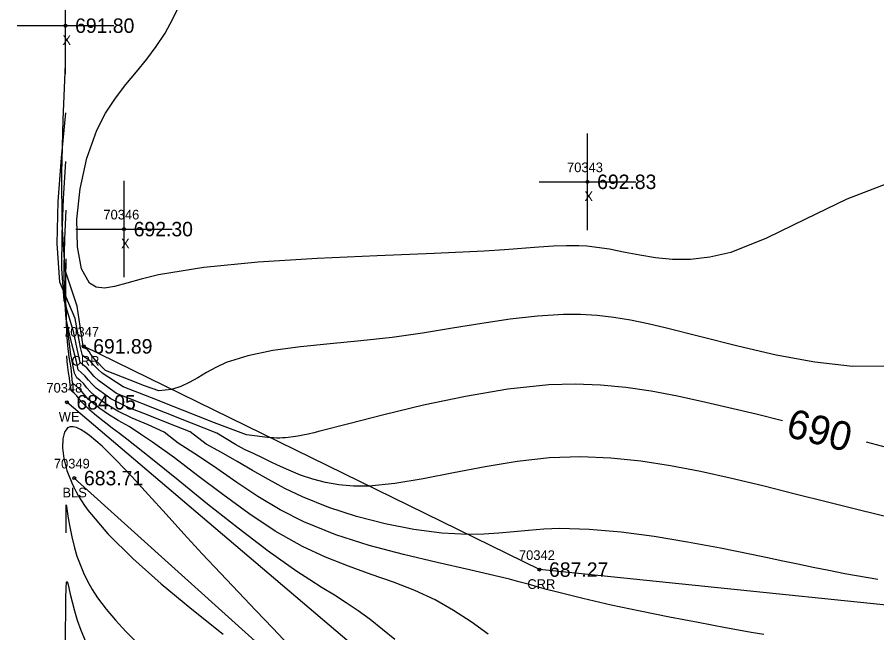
# Model space of a CAD drawing. Extents: x 1376587 to 1378239, y 1000335 to 1003031.
# Drawn here: x 1376921.1 to 1377010.1, y 1001560.2 to 1001624.1 of the extents above; entities that cross this region are included whole.
import ezdxf

# ---------------------------------------------------------------- set-up
doc = ezdxf.new("R2010")
doc.units = 0
for name, color, linetype in [('RD_DTM_BkLn1', 7, 'Continuous'), ('RD_DTM_BkLn_txCode', 7, 'Continuous'), ('RD_DTM_Major1', 7, 'Continuous'), ('RD_DTM_Major1_Lbl', 7, 'Continuous'), ('RD_DTM_Minor1', 7, 'Continuous'), ('RD_EX_H2O', 7, 'Continuous'), ('RD_EX_H2O_txCode', 7, 'Continuous'), ('RD_EX_Misc', 7, 'Continuous'), ('RD_EX_Misc_txCode', 7, 'Continuous'), ('RD_EX_TX_H2O_ELEV', 7, 'Continuous'), ('RD_EX_TX_Misc_ELEV', 7, 'Continuous'), ('RD_SMD_Locator', 7, 'Continuous')]:
    doc.layers.add(name, color=color, linetype=linetype)

msp = doc.modelspace()

# ---------------------------------------------------------------- linework, layer by layer
at = {"layer": 'RD_DTM_BkLn1'}
msp.add_lwpolyline([(1377322.969, 1001642.525), (1377293.605, 1001607.098), (1377249.432, 1001558.553), (1377170.427, 1001571.461), (1377111.377, 1001551.766), (1377054.733, 1001532.92), (1377033.73, 1001527.24), (1376971.435, 1001536.185), (1376926.988, 1001576.278)], dxfattribs=at)
at = {"layer": 'RD_DTM_Major1'}
for points in [[(1377000.334, 1001582.221), (1376997.598, 1001582.904), (1376992.398, 1001584.13), (1376989.479, 1001584.764), (1376986.737, 1001585.286), (1376984.1, 1001585.679), (1376981.502, 1001585.928), (1376978.871, 1001586.017), (1376976.139, 1001585.93), (1376971.904, 1001585.484), (1376967.51, 1001584.744), (1376963.162, 1001583.824), (1376959.062, 1001582.84), (1376955.414, 1001581.903), (1376952.422, 1001581.129), (1376951.799, 1001580.975), (1376951.22, 1001580.838), (1376950.674, 1001580.72), (1376950.152, 1001580.621), (1376949.642, 1001580.542), (1376949.135, 1001580.483), (1376948.85, 1001580.46), (1376948.56, 1001580.443), (1376948.261, 1001580.434), (1376947.952, 1001580.433), (1376947.629, 1001580.44), (1376947.29, 1001580.456), (1376944.84, 1001580.749), (1376941.5, 1001582.016), (1376938.18, 1001583.329), (1376934.972, 1001584.596), (1376932.063, 1001585.747), (1376929.864, 1001587.148), (1376929.433, 1001587.558), (1376929.027, 1001587.98), (1376928.645, 1001588.417), (1376928.153, 1001588.749), (1376927.824, 1001588.986), (1376927.641, 1001589.822), (1376927.095, 1001592.833), (1376925.495, 1001596.579), (1376925.218, 1001600.613), (1376925.31, 1001604.95), (1376925.647, 1001609.49), (1376926.106, 1001614.13)], [(1376960.172, 1001559.561), (1376957.617, 1001561.634), (1376956.382, 1001562.524), (1376955.155, 1001563.346), (1376953.923, 1001564.131), (1376952.67, 1001564.914), (1376951.381, 1001565.728), (1376950.043, 1001566.606), (1376947.072, 1001568.713), (1376943.947, 1001571.091), (1376940.794, 1001573.592), (1376937.742, 1001576.062), (1376934.917, 1001578.352), (1376932.446, 1001580.31), (1376931.653, 1001580.918), (1376930.923, 1001581.47), (1376930.254, 1001581.976), (1376929.646, 1001582.446), (1376929.095, 1001582.888), (1376928.602, 1001583.313), (1376928.203, 1001583.689), (1376927.848, 1001584.063), (1376927.536, 1001584.439), (1376927.264, 1001584.821), (1376926.978, 1001585.068), (1376926.681, 1001585.324), (1376926.563, 1001585.932), (1376926.506, 1001586.667), (1376926.399, 1001587.221), (1376926.318, 1001587.788), (1376926.254, 1001588.364), (1376926.199, 1001588.945)], [(1377014.23, 1001578.619), (1377009.053, 1001579.989)], [(1376926.158, 1001570.618), (1376926.138, 1001572.011), (1376926.133, 1001572.606), (1376926.133, 1001573.079), (1376926.141, 1001573.389), (1376926.158, 1001573.496), (1376926.196, 1001573.318), (1376926.261, 1001572.84), (1376926.363, 1001572.118), (1376926.514, 1001571.21), (1376926.723, 1001570.172), (1376927.001, 1001569.06), (1376927.265, 1001568.199), (1376927.579, 1001567.331), (1376927.946, 1001566.461), (1376928.37, 1001565.593), (1376928.854, 1001564.729), (1376929.403, 1001563.873), (1376930.278, 1001562.699), (1376931.262, 1001561.538), (1376932.335, 1001560.383), (1376933.473, 1001559.224)]]:
    msp.add_lwpolyline(points, dxfattribs=at)
at = {"layer": 'RD_DTM_Minor1'}
for points in [[(1377011.508, 1001606.935), (1377007.009, 1001605.182), (1377002.717, 1001603.12), (1376998.688, 1001601.152), (1376994.979, 1001599.681), (1376992.822, 1001599.164), (1376990.808, 1001598.941), (1376988.931, 1001598.947), (1376987.184, 1001599.116), (1376985.562, 1001599.382), (1376984.057, 1001599.681), (1376983.232, 1001599.845), (1376982.431, 1001599.993), (1376981.644, 1001600.122), (1376980.858, 1001600.227), (1376980.06, 1001600.305), (1376979.239, 1001600.351), (1376977.976, 1001600.358), (1376976.607, 1001600.305), (1376975.099, 1001600.208), (1376971.548, 1001599.94), (1376969.443, 1001599.802), (1376964.274, 1001599.554), (1376958.375, 1001599.322), (1376952.157, 1001599.045), (1376946.031, 1001598.663), (1376940.409, 1001598.115), (1376935.701, 1001597.34), (1376933.93, 1001596.901), (1376932.421, 1001596.476), (1376931.152, 1001596.145), (1376930.099, 1001595.983), (1376929.238, 1001596.07), (1376928.548, 1001596.481), (1376927.736, 1001597.961), (1376927.31, 1001600.259), (1376927.263, 1001603.112), (1376927.589, 1001606.256), (1376928.28, 1001609.427), (1376929.33, 1001612.361), (1376930.23, 1001614.095), (1376931.243, 1001615.649), (1376932.322, 1001617.07), (1376933.42, 1001618.406), (1376934.489, 1001619.705), (1376935.483, 1001621.013), (1376936.397, 1001622.418), (1376937.2, 1001623.875), (1376937.916, 1001625.372)], [(1377011.261, 1001587.866), (1377007.585, 1001587.855), (1377003.689, 1001588.285), (1376999.693, 1001589.027), (1376995.72, 1001589.951), (1376991.892, 1001590.929), (1376988.331, 1001591.831), (1376986.42, 1001592.273), (1376984.607, 1001592.64), (1376982.857, 1001592.927), (1376981.137, 1001593.126), (1376979.411, 1001593.232), (1376977.648, 1001593.241), (1376974.958, 1001593.076), (1376972.135, 1001592.745), (1376969.198, 1001592.303), (1376966.169, 1001591.805), (1376963.069, 1001591.307), (1376959.917, 1001590.862), (1376956.679, 1001590.502), (1376953.486, 1001590.194), (1376950.418, 1001589.876), (1376947.551, 1001589.488), (1376944.963, 1001588.966), (1376942.733, 1001588.249), (1376941.664, 1001587.751), (1376940.694, 1001587.213), (1376939.785, 1001586.675), (1376938.902, 1001586.179), (1376938.006, 1001585.764), (1376937.061, 1001585.47), (1376935.756, 1001585.322), (1376934.261, 1001585.848), (1376932.778, 1001586.436), (1376930.224, 1001587.445), (1376929.105, 1001588.571), (1376928.901, 1001588.833), (1376928.704, 1001589.106), (1376928.514, 1001589.39), (1376928.307, 1001589.66), (1376928.047, 1001589.761), (1376927.91, 1001589.966), (1376927.287, 1001594.103), (1376926.053, 1001597.826), (1376925.72, 1001602.609), (1376925.68, 1001607.866), (1376925.835, 1001613.437), (1376926.088, 1001619.167)], [(1377011.573, 1001572.157), (1377008.323, 1001572.948), (1377005.013, 1001573.778), (1377001.665, 1001574.624), (1376998.299, 1001575.46), (1376994.936, 1001576.263), (1376991.84, 1001576.952), (1376988.751, 1001577.555), (1376985.657, 1001578.035), (1376982.545, 1001578.356), (1376979.403, 1001578.48), (1376976.216, 1001578.372), (1376972.875, 1001578.001), (1376969.537, 1001577.446), (1376966.269, 1001576.809), (1376963.133, 1001576.194), (1376960.194, 1001575.703), (1376957.518, 1001575.442), (1376955.891, 1001575.438), (1376954.39, 1001575.567), (1376952.994, 1001575.814), (1376951.68, 1001576.161), (1376950.427, 1001576.592), (1376949.213, 1001577.091), (1376948.338, 1001577.489), (1376947.456, 1001577.909), (1376946.553, 1001578.346), (1376945.613, 1001578.795), (1376944.62, 1001579.251), (1376943.674, 1001579.746), (1376941.755, 1001580.944), (1376939.128, 1001581.983), (1376936.44, 1001583.046), (1376931.371, 1001585.049), (1376929.479, 1001586.406), (1376929.057, 1001586.818), (1376928.665, 1001587.248), (1376928.303, 1001587.698), (1376927.876, 1001588.01), (1376927.58, 1001588.265), (1376927.381, 1001589.191), (1376926.91, 1001591.464), (1376925.935, 1001594.672), (1376925.713, 1001597.975), (1376925.722, 1001601.536), (1376925.885, 1001605.271), (1376926.125, 1001609.093)], [(1377010.212, 1001565.76), (1377006.807, 1001566.365), (1377005.129, 1001566.688), (1377003.518, 1001567.013), (1377001.942, 1001567.342), (1377000.37, 1001567.677), (1376998.772, 1001568.019), (1376997.116, 1001568.368), (1376993.908, 1001569.018), (1376990.517, 1001569.651), (1376987.052, 1001570.217), (1376983.62, 1001570.67), (1376980.328, 1001570.96), (1376977.284, 1001571.039), (1376975.619, 1001570.974), (1376974.039, 1001570.849), (1376972.503, 1001570.699), (1376970.97, 1001570.556), (1376969.398, 1001570.455), (1376967.746, 1001570.427), (1376965.052, 1001570.578), (1376962.173, 1001570.953), (1376959.2, 1001571.535), (1376956.224, 1001572.304), (1376953.338, 1001573.242), (1376950.631, 1001574.329), (1376948.808, 1001575.204), (1376947.095, 1001576.125), (1376945.454, 1001577.069), (1376943.851, 1001578.012), (1376942.251, 1001578.93), (1376940.634, 1001579.811), (1376938.986, 1001581.068), (1376936.787, 1001581.937), (1376934.629, 1001582.791), (1376932.556, 1001583.61), (1376930.757, 1001584.493), (1376929.265, 1001585.611), (1376928.841, 1001586.014), (1376928.45, 1001586.438), (1376928.094, 1001586.887), (1376927.711, 1001587.225), (1376927.405, 1001587.488), (1376927.212, 1001588.378), (1376926.719, 1001590.191), (1376926.16, 1001592.752), (1376925.973, 1001595.349), (1376925.943, 1001598.142), (1376926.017, 1001601.066), (1376926.144, 1001604.056)], [(1376998.4, 1001560.052), (1376997.098, 1001560.287), (1376995.79, 1001560.524), (1376994.453, 1001560.768), (1376991.61, 1001561.295), (1376988.637, 1001561.865), (1376985.606, 1001562.473), (1376982.589, 1001563.114), (1376979.658, 1001563.783), (1376976.886, 1001564.475), (1376975.906, 1001564.738), (1376974.946, 1001565.002), (1376973.991, 1001565.266), (1376973.03, 1001565.53), (1376972.049, 1001565.792), (1376971.034, 1001566.052), (1376967.939, 1001566.776), (1376964.585, 1001567.522), (1376961.082, 1001568.34), (1376957.54, 1001569.281), (1376954.067, 1001570.396), (1376950.775, 1001571.735), (1376948.311, 1001572.999), (1376946.006, 1001574.381), (1376943.828, 1001575.821), (1376941.747, 1001577.26), (1376939.734, 1001578.636), (1376937.758, 1001579.89), (1376936.285, 1001581.032), (1376934.636, 1001581.816), (1376932.966, 1001582.477), (1376931.5, 1001583.213), (1376930.202, 1001583.999), (1376929.079, 1001584.842), (1376928.658, 1001585.23), (1376928.275, 1001585.64), (1376927.929, 1001586.075), (1376927.572, 1001586.414), (1376927.259, 1001586.684), (1376927.02, 1001587.141), (1376926.627, 1001589.084), (1376926.427, 1001590.729), (1376926.165, 1001592.715), (1376926.107, 1001594.745), (1376926.117, 1001596.86), (1376926.162, 1001599.019)], [(1376969.865, 1001560.112), (1376968.091, 1001561.367), (1376966.265, 1001562.568), (1376964.353, 1001563.656), (1376962.246, 1001564.625), (1376960.034, 1001565.48), (1376957.741, 1001566.291), (1376955.391, 1001567.131), (1376953.007, 1001568.073), (1376950.615, 1001569.188), (1376947.809, 1001570.789), (1376945.052, 1001572.62), (1376942.373, 1001574.57), (1376939.8, 1001576.526), (1376937.362, 1001578.376), (1376935.087, 1001580.008), (1376933.828, 1001580.833), (1376932.663, 1001581.61), (1376931.547, 1001582.237), (1376930.541, 1001582.865), (1376929.638, 1001583.477), (1376928.844, 1001584.099), (1376928.438, 1001584.474), (1376928.07, 1001584.865), (1376927.741, 1001585.276), (1376927.422, 1001585.615), (1376927.112, 1001585.882), (1376926.815, 1001586.138), (1376926.657, 1001587.693), (1376926.44, 1001588.821), (1376926.304, 1001590.036), (1376926.229, 1001591.316), (1376926.195, 1001592.638), (1376926.181, 1001593.982)], [(1376949.224, 1001558.969), (1376947.549, 1001560.73), (1376945.799, 1001562.561), (1376943.988, 1001564.459), (1376942.13, 1001566.418), (1376940.24, 1001568.434), (1376938.333, 1001570.504), (1376936.49, 1001572.537), (1376934.683, 1001574.539), (1376932.95, 1001576.432), (1376931.328, 1001578.141), (1376929.858, 1001579.587), (1376928.576, 1001580.694), (1376928.08, 1001581.055), (1376927.629, 1001581.331), (1376927.224, 1001581.516), (1376926.866, 1001581.606), (1376926.557, 1001581.596), (1376926.296, 1001581.482), (1376925.965, 1001581.042), (1376925.786, 1001580.331), (1376925.766, 1001579.4), (1376925.911, 1001578.299), (1376926.225, 1001577.08), (1376926.716, 1001575.792), (1376926.933, 1001575.329), (1376927.173, 1001574.864), (1376927.438, 1001574.396), (1376927.727, 1001573.923), (1376928.043, 1001573.446), (1376928.386, 1001572.963), (1376930.451, 1001570.507), (1376933.037, 1001567.949), (1376935.992, 1001565.332), (1376939.168, 1001562.696), (1376942.413, 1001560.084)], [(1376926.091, 1001558.526), (1376926.091, 1001560.509), (1376926.097, 1001562.295), (1376926.114, 1001563.786), (1376926.146, 1001564.883), (1376926.195, 1001565.487), (1376926.247, 1001565.572), (1376926.32, 1001565.366), (1376926.423, 1001564.913), (1376926.565, 1001564.257), (1376926.753, 1001563.441), (1376926.998, 1001562.51), (1376927.296, 1001561.539), (1376927.66, 1001560.513), (1376928.097, 1001559.444)]]:
    msp.add_lwpolyline(points, dxfattribs=at)
at = {"layer": 'RD_EX_H2O'}
for points in [[(1377371.252, 1001717.109), (1377370.663, 1001706.746), (1377369.728, 1001695.357), (1377362.942, 1001684.236), (1377342.423, 1001669.398), (1377312.741, 1001659.466), (1377279.928, 1001621.341), (1377233.434, 1001598.677), (1377169.941, 1001585.879), (1377114.813, 1001581.379), (1377057.35, 1001560.459), (1377030.227, 1001561.127), (1376975.162, 1001566.792), (1376927.948, 1001589.938)], [(1377334.456, 1001660.576), (1377318.223, 1001649.936), (1377286.502, 1001611.675), (1377286.502, 1001611.675), (1377237.873, 1001575.182), (1377169.705, 1001581.472), (1377109.998, 1001563.579), (1377053.341, 1001538.726), (1377032.875, 1001532.424), (1376974.355, 1001543.191), (1376926.217, 1001584.14)]]:
    msp.add_lwpolyline(points, dxfattribs=at)
at = {"layer": 'RD_EX_Misc'}
for p, q in [((1376926.073, 1001618.181), (1376926.073, 1001628.181)), ((1376921.073, 1001623.181), (1376931.073, 1001623.181)), ((1376980.14, 1001601.992), (1376980.14, 1001611.992)), ((1376932.142, 1001597.091), (1376932.142, 1001607.091)), ((1376975.14, 1001606.992), (1376985.14, 1001606.992)), ((1376927.142, 1001602.091), (1376937.142, 1001602.091))]:
    msp.add_line(p, q, dxfattribs=at)
at = {"layer": 'RD_SMD_Locator'}
for centre in [(1376926.073, 1001623.181), (1376980.14, 1001606.992), (1376932.142, 1001602.091), (1376927.948, 1001589.938), (1376926.217, 1001584.14), (1376926.988, 1001576.278), (1376975.162, 1001566.792)]:
    msp.add_circle(centre, 0.15, dxfattribs=at)

# ---------------------------------------------------------------- texts
at = {"layer": 'RD_DTM_BkLn_txCode'}
for s, p in [('70349', (1376924.87, 1001577.278)), ('BLS', (1376925.76, 1001574.278))]:
    msp.add_text(s, height=1, dxfattribs=at).set_placement(p)
at = {"layer": 'RD_DTM_Major1_Lbl'}
msp.add_text('690', height=3, rotation=345.63997, dxfattribs=at).set_placement((1377000.572, 1001580.625))
at = {"layer": 'RD_EX_H2O_txCode'}
for s, p in [('70347', (1376925.83, 1001590.938)), ('CRR', (1376926.696, 1001587.938)), ('70348', (1376924.099, 1001585.14)), ('WE', (1376925.378, 1001582.14)), ('70342', (1376973.044, 1001567.792)), ('CRR', (1376973.91, 1001564.792))]:
    msp.add_text(s, height=1, dxfattribs=at).set_placement(p)
at = {"layer": 'RD_EX_Misc_txCode'}
for s, p in [('X', (1376925.758, 1001621.181)), ('70343', (1376978.022, 1001607.992)), ('X', (1376979.825, 1001604.992)), ('70346', (1376930, 1001603.091)), ('X', (1376931.827, 1001600.091))]:
    msp.add_text(s, height=1, dxfattribs=at).set_placement(p)
at = {"layer": 'RD_EX_TX_H2O_ELEV'}
for s, p in [('691.89', (1376928.948, 1001589.188)), ('684.05', (1376927.217, 1001583.39)), ('687.27', (1376976.162, 1001566.042))]:
    msp.add_text(s, height=1.5, dxfattribs=at).set_placement(p)
at = {"layer": 'RD_EX_TX_Misc_ELEV'}
for s, p in [('691.80', (1376927.073, 1001622.431)), ('692.83', (1376981.14, 1001606.242)), ('692.30', (1376933.142, 1001601.341)), ('683.71', (1376927.988, 1001575.528))]:
    msp.add_text(s, height=1.5, dxfattribs=at).set_placement(p)

doc.saveas('drawing.dxf')
